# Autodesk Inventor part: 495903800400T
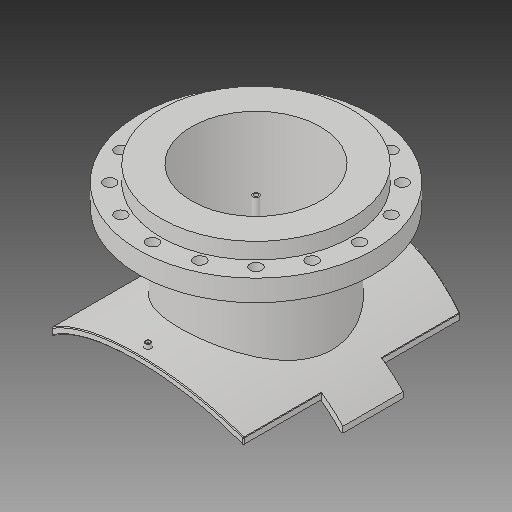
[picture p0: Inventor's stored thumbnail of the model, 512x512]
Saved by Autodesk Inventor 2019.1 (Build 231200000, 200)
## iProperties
Created: 2017-10
Part Number: 495903800400T
Material: Generic
Description: PLASSON FLANGED BRANCH SADDLE 800X400
Document SubType Name: Modeling
Designer: KIM
Mass: 2339.99 g
Surface Area: 3251.55 cm^2
Volume: 2339.99 cm^3
Density: 1 g/cm^3
Appearance: Default
Author: KIM
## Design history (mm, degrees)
derived "495904_495903.ipt"
feature "Solid1::495904_495903.ipt"
feature "Solid2::495904_495903.ipt"
tag "TaggingFeature1"
body "Solid1"
other parameters: "d1" = 15, "d2" = 486, "d4" = 0, "d6" = 152.5, "d7" = 0, "d12" = 425.6, "d13" = 14, "d14" = 274.5, "d16" = 5 deg, "d18" = 4, "d19" = 14, "d20" = 0, "d21" = 3, "d22" = 0, "d23" = 695, "d36" = 274.5, "d38" = 0, "d39" = 2, "d41" = 327, "d42" = 482, "d43" = 595, "d44" = 224, "d46" = 385.6, "d47" = 16, "d48" = 10.4, "d49" = 196, "d51" = 816, "d53" = 0, "d55" = 262.5, "d57" = 0, "d59" = 360 deg, "d61" = 54, "d63" = 0, "d67" = 15, "d70" = 0, "d71" = 2, "d_1" = 482, "x_" = 15, "D_" = 16, "DN_" = 327, "D_1" = 595, "t_" = 54, "Dp_" = 525
